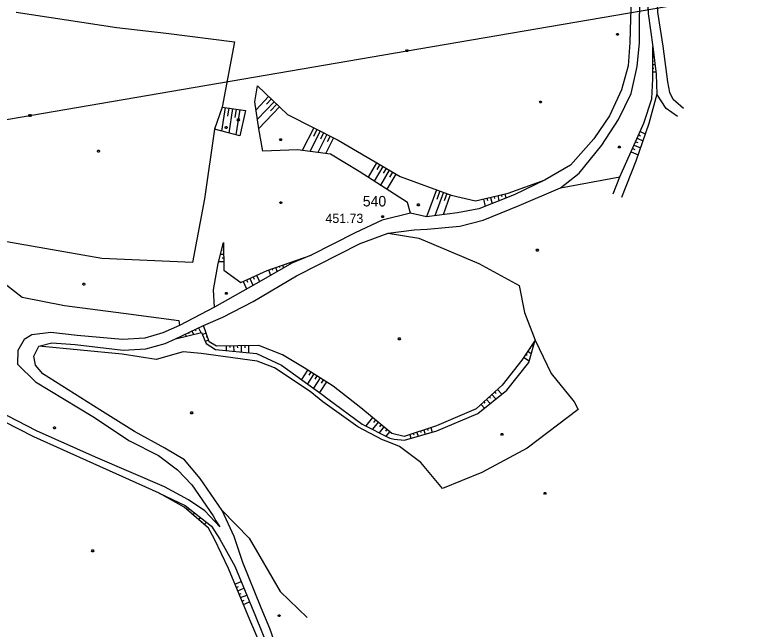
# Model space of a CAD drawing. Extents: x -664960 to -662754, y -993849 to -991145.
# Drawn here: x -662991.3 to -662754.2, y -992772.1 to -992572.6 of the extents above; entities that cross this region are included whole.
import ezdxf

# ---------------------------------------------------------------- set-up
doc = ezdxf.new("R2010")
doc.units = 0
for name, color, linetype in [('Vrstva 1', 7, 'Continuous'), ('Vrstva 13', 7, 'Continuous'), ('Vrstva 27', 7, 'Continuous'), ('Vrstva 37', 7, 'Continuous'), ('Vrstva 57', 7, 'Continuous'), ('Vrstva 63', 7, 'Continuous'), ('Vrstva 8', 7, 'Continuous')]:
    doc.layers.add(name, color=color, linetype=linetype)

msp = doc.modelspace()

# ---------------------------------------------------------------- linework, layer by layer
at = {"layer": 'Vrstva 13'}
for points in [[(-662820.269, -992600.671), (-662820.089, -992600.971), (-662820.269, -992601.271), (-662820.629, -992601.271), (-662820.809, -992600.971), (-662820.629, -992600.671), (-662820.269, -992600.671)], [(-662904.678, -992612.889), (-662904.498, -992613.189), (-662904.678, -992613.489), (-662905.038, -992613.489), (-662905.218, -992613.189), (-662905.038, -992612.889), (-662904.678, -992612.889)], [(-662794.695, -992615.239), (-662794.515, -992615.539), (-662794.695, -992615.839), (-662795.055, -992615.839), (-662795.235, -992615.539), (-662795.055, -992615.239), (-662794.695, -992615.239)], [(-662963.83, -992616.631), (-662963.65, -992616.931), (-662963.83, -992617.231), (-662964.19, -992617.231), (-662964.37, -992616.931), (-662964.19, -992616.631), (-662963.83, -992616.631)], [(-662904.616, -992633.337), (-662904.436, -992633.637), (-662904.616, -992633.937), (-662904.976, -992633.937), (-662905.156, -992633.637), (-662904.976, -992633.337), (-662904.616, -992633.337)], [(-662859.938, -992634.055), (-662859.758, -992634.355), (-662859.938, -992634.655), (-662860.298, -992634.655), (-662860.478, -992634.355), (-662860.298, -992634.055), (-662859.938, -992634.055)], [(-662821.298, -992648.724), (-662821.118, -992649.024), (-662821.298, -992649.324), (-662821.658, -992649.324), (-662821.838, -992649.024), (-662821.658, -992648.724), (-662821.298, -992648.724)], [(-662968.594, -992659.789), (-662968.414, -992660.089), (-662968.594, -992660.389), (-662968.954, -992660.389), (-662969.134, -992660.089), (-662968.954, -992659.789), (-662968.594, -992659.789)], [(-662922.343, -992662.749), (-662922.163, -992663.049), (-662922.343, -992663.349), (-662922.703, -992663.349), (-662922.883, -992663.049), (-662922.703, -992662.749), (-662922.343, -992662.749)], [(-662866.16, -992677.539), (-662865.98, -992677.839), (-662866.16, -992678.139), (-662866.52, -992678.139), (-662866.7, -992677.839), (-662866.52, -992677.539), (-662866.16, -992677.539)], [(-662933.542, -992701.554), (-662933.362, -992701.854), (-662933.542, -992702.154), (-662933.902, -992702.154), (-662934.082, -992701.854), (-662933.902, -992701.554), (-662933.542, -992701.554)], [(-662978.123, -992706.427), (-662977.943, -992706.727), (-662978.123, -992707.027), (-662978.483, -992707.027), (-662978.663, -992706.727), (-662978.483, -992706.427), (-662978.123, -992706.427)], [(-662832.81, -992708.515), (-662832.63, -992708.815), (-662832.81, -992709.115), (-662833.17, -992709.115), (-662833.35, -992708.815), (-662833.17, -992708.515), (-662832.81, -992708.515)], [(-662818.857, -992727.658), (-662818.677, -992727.958), (-662818.857, -992728.258), (-662819.217, -992728.258), (-662819.397, -992727.958), (-662819.217, -992727.658), (-662818.857, -992727.658)], [(-662965.695, -992746.303), (-662965.515, -992746.603), (-662965.695, -992746.903), (-662966.055, -992746.903), (-662966.235, -992746.603), (-662966.055, -992746.303), (-662965.695, -992746.303)], [(-662905.166, -992767.399), (-662904.986, -992767.699), (-662905.166, -992767.999), (-662905.526, -992767.999), (-662905.706, -992767.699), (-662905.526, -992767.399), (-662905.166, -992767.399)]]:
    msp.add_lwpolyline(points, dxfattribs=at)
at = {"layer": 'Vrstva 27'}
for points in [[(-662783.31, -992523.58), (-662785.46, -992536.18), (-662786.51, -992550.42), (-662785.54, -992572.27), (-662783.94, -992583.1)], [(-662814.02, -992628.77), (-662807.9, -992624.04), (-662800.53, -992615), (-662795.19, -992606.64), (-662791.07, -992598.2), (-662789.03, -992589.4), (-662788.34, -992581.72), (-662788.3, -992573.38), (-662787.39, -992550.45), (-662786.57, -992536.01), (-662787.99, -992526.89)], [(-662773.98, -992603.1), (-662777.38, -992600.19), (-662778.5, -992597.92), (-662779.16, -992594.44), (-662780.59, -992582.88), (-662782.36, -992571.76), (-662783.36, -992550.29), (-662782.46, -992536.59), (-662780.37, -992526.63)], [(-662790.37, -992550.8), (-662791.29, -992573.99), (-662791.42, -992581.67), (-662792.03, -992589.2), (-662794.12, -992596.99), (-662798.03, -992605.48), (-662803.2, -992612.92), (-662810.72, -992621.51), (-662818.96, -992626.26)], [(-662775.95, -992605.62), (-662779.61, -992603.11), (-662782.69, -992598.42)], [(-662839.12, -992639.35), (-662827.35, -992634.53), (-662814.02, -992628.77)], [(-662862.68, -992637.01), (-662871.9, -992639.26), (-662880.6, -992643.45), (-662894.95, -992650.64)], [(-662920, -992741.98), (-662923.87, -992733.57), (-662931.03, -992723.19), (-662936.1, -992717.15), (-662942.41, -992713.3), (-662952.34, -992707.86), (-662963.59, -992700.84), (-662982.13, -992689.15), (-662984.42, -992686.38), (-662985.05, -992683.42), (-662983.4, -992680.23), (-662979.18, -992679.11), (-662971.61, -992679.66), (-662956.04, -992681.53), (-662948.6, -992681.11), (-662942.34, -992679.34), (-662939.04, -992677.84), (-662929.94, -992673.49), (-662923.58, -992670.74), (-662913.79, -992665.67), (-662899.69, -992657.43), (-662879.01, -992646.88), (-662869.94, -992643.5), (-662861.52, -992642.43), (-662857.22, -992642.21), (-662846.7, -992641.27), (-662839.12, -992639.35)], [(-662926.37, -992667.52), (-662937.65, -992673.51), (-662943.13, -992675.85), (-662949, -992677.64), (-662956.17, -992678.08), (-662970.95, -992676.78), (-662979.5, -992675.73), (-662985.63, -992676.49), (-662988.09, -992678.08), (-662990.2, -992681.58), (-662990.26, -992686.06), (-662984.45, -992691.79), (-662965.81, -992703.08), (-662953.95, -992710.94), (-662944.54, -992715.73), (-662938.37, -992720.36), (-662933.71, -992725.23), (-662926.81, -992735.29), (-662925.91, -992736.91), (-662924.58, -992738.79)], [(-662899.77, -992799.69), (-662904.47, -992782.92), (-662908.32, -992771.87), (-662911.16, -992765.16), (-662917.17, -992750.4), (-662920, -992741.98)]]:
    msp.add_lwpolyline(points, dxfattribs=at)
at = {"layer": 'Vrstva 37'}
for points in [[(-662863.64, -992584.02), (-662863.46, -992584.32), (-662863.64, -992584.62), (-662864, -992584.62), (-662864.18, -992584.32), (-662864, -992584.02), (-662863.64, -992584.02)], [(-662986.1, -992605.06), (-662985.92, -992605.36), (-662986.1, -992605.66), (-662986.46, -992605.66), (-662986.64, -992605.36), (-662986.46, -992605.06), (-662986.1, -992605.06)]]:
    msp.add_lwpolyline(points, dxfattribs=at)
at = {"layer": 'Vrstva 57'}
msp.add_lwpolyline([(-663665.051, -992722.016), (-663550.65, -992702.35), (-663440.01, -992683.39), (-663326.32, -992663.75), (-663217.09, -992644.97), (-663109.78, -992626.53), (-662986.28, -992605.36), (-662863.82, -992584.32), (-662754.25, -992565.49)], dxfattribs=at)
at = {"layer": 'Vrstva 63'}
for p, q in [((-662783.958, -992585.146), (-662783.871, -992585.147)), ((-662783.947, -992583.946), (-662783.84, -992583.947)), ((-662783.979, -992587.546), (-662783.79, -992587.547)), ((-662783.968, -992586.346), (-662783.555, -992586.349)), ((-662783.999, -992589.946), (-662783.709, -992589.948)), ((-662783.989, -992588.746), (-662783.27, -992588.752)), ((-662784.01, -992591.146), (-662782.985, -992591.155)), ((-662908.75, -992599.197), (-662912.826, -992603.488)), ((-662907.01, -992600.85), (-662912.374, -992606.497)), ((-662907.88, -992600.024), (-662909.452, -992601.678)), ((-662906.14, -992601.677), (-662908.141, -992603.783)), ((-662922.877, -992602.728), (-662924.023, -992610.412)), ((-662921.69, -992602.904), (-662922.078, -992605.506)), ((-662920.503, -992603.081), (-662921.687, -992611.022)), ((-662919.317, -992603.258), (-662919.717, -992605.945)), ((-662918.13, -992603.435), (-662919.352, -992611.633)), ((-662905.27, -992602.503), (-662911.923, -992609.507)), ((-662894.121, -992609.308), (-662897.856, -992616.719)), ((-662891.978, -992610.388), (-662895.338, -992617.055)), ((-662893.05, -992609.848), (-662894.231, -992612.192)), ((-662889.835, -992611.468), (-662892.82, -992617.391)), ((-662890.906, -992610.928), (-662891.963, -992613.024)), ((-662788.076, -992610.558), (-662786.46, -992611.281)), ((-662887.692, -992612.548), (-662890.302, -992617.728)), ((-662888.763, -992612.008), (-662889.695, -992613.857)), ((-662789.545, -992613.845), (-662788.908, -992614.13)), ((-662789.055, -992612.749), (-662787.241, -992613.561)), ((-662788.565, -992611.654), (-662787.994, -992611.909)), ((-662790.525, -992616.036), (-662789.821, -992616.35)), ((-662790.035, -992614.94), (-662788.021, -992615.841)), ((-662791.015, -992617.131), (-662788.802, -992618.121)), ((-662873.698, -992620.671), (-662876.471, -992625.374)), ((-662871.63, -992621.89), (-662874.45, -992626.67)), ((-662872.664, -992621.281), (-662873.595, -992622.859)), ((-662869.563, -992623.11), (-662872.428, -992627.967)), ((-662870.597, -992622.5), (-662871.543, -992624.104)), ((-662867.496, -992624.329), (-662870.406, -992629.263)), ((-662868.53, -992623.719), (-662869.491, -992625.349)), ((-662814.02, -992628.77), (-662794.65, -992625.26)), ((-662854.27, -992629.426), (-662857.46, -992638.27)), ((-662852.013, -992630.24), (-662854.777, -992637.906)), ((-662853.141, -992629.833), (-662854.133, -992632.582)), ((-662849.755, -992631.054), (-662852.095, -992637.543)), ((-662850.884, -992630.647), (-662851.734, -992633.004)), ((-662839.031, -992632.459), (-662838.463, -992634.861)), ((-662837.863, -992632.183), (-662837.687, -992632.927)), ((-662836.695, -992631.907), (-662836.206, -992633.974)), ((-662835.528, -992631.63), (-662835.378, -992632.263)), ((-662834.36, -992631.354), (-662833.95, -992633.087)), ((-662833.192, -992631.078), (-662833.069, -992631.599)), ((-662832.024, -992630.802), (-662831.694, -992632.2)), ((-662923.394, -992648.007), (-662923.783, -992648.011)), ((-662923.381, -992649.207), (-662923.619, -992649.209)), ((-662923.367, -992650.407), (-662924.409, -992650.418)), ((-662923.354, -992651.607), (-662923.81, -992651.612)), ((-662923.341, -992652.807), (-662925.036, -992652.825)), ((-662904.228, -992653.869), (-662903.909, -992654.785)), ((-662903.095, -992653.474), (-662903.013, -992653.71)), ((-662901.961, -992653.08), (-662901.788, -992653.578)), ((-662908.761, -992655.446), (-662908.151, -992657.2)), ((-662907.628, -992655.052), (-662907.449, -992655.566)), ((-662906.495, -992654.658), (-662906.03, -992655.992)), ((-662905.361, -992654.263), (-662905.231, -992654.638)), ((-662915.946, -992658.704), (-662915.591, -992659.474)), ((-662914.857, -992658.202), (-662913.832, -992660.423)), ((-662913.767, -992657.699), (-662913.44, -992658.409)), ((-662912.677, -992657.196), (-662911.736, -992659.237)), ((-662917.036, -992659.207), (-662915.928, -992661.609)), ((-662933.677, -992675.276), (-662933.14, -992676.4)), ((-662932.595, -992674.759), (-662932.38, -992675.209)), ((-662931.512, -992674.241), (-662930.758, -992675.818)), ((-662938.008, -992677.347), (-662937.905, -992677.563)), ((-662936.925, -992676.829), (-662936.855, -992676.977)), ((-662935.843, -992676.312), (-662935.522, -992676.981)), ((-662934.76, -992675.794), (-662934.617, -992676.093)), ((-662929.05, -992676.014), (-662930.275, -992676.446)), ((-662928.651, -992677.146), (-662929.036, -992677.282)), ((-662928.251, -992678.277), (-662929.342, -992678.662)), ((-662922.525, -992680.147), (-662922.505, -992681.644)), ((-662921.325, -992680.13), (-662921.318, -992680.673)), ((-662920.126, -992680.113), (-662920.101, -992681.876)), ((-662918.926, -992680.097), (-662918.917, -992680.728)), ((-662917.726, -992680.08), (-662917.698, -992682.109)), ((-662916.526, -992680.064), (-662916.516, -992680.783)), ((-662915.326, -992680.047), (-662915.294, -992682.341)), ((-662823.261, -992679.841), (-662822.765, -992680.176)), ((-662824.604, -992681.83), (-662823.468, -992682.598)), ((-662823.933, -992680.836), (-662823.661, -992681.019)), ((-662825.948, -992683.819), (-662824.172, -992685.019)), ((-662825.276, -992682.825), (-662824.791, -992683.152)), ((-662896.102, -992687.942), (-662898.04, -992691.047)), ((-662894.066, -992689.213), (-662896.09, -992692.456)), ((-662895.084, -992688.577), (-662895.744, -992689.634)), ((-662892.03, -992690.484), (-662894.14, -992693.864)), ((-662893.048, -992689.848), (-662893.736, -992690.951)), ((-662889.994, -992691.755), (-662892.191, -992695.273)), ((-662891.012, -992691.12), (-662891.729, -992692.268)), ((-662834.475, -992694.241), (-662833.056, -992695.784)), ((-662837.125, -992696.677), (-662836.708, -992697.131)), ((-662836.242, -992695.865), (-662834.934, -992697.288)), ((-662835.358, -992695.053), (-662834.904, -992695.547)), ((-662839.776, -992699.114), (-662838.689, -992700.295)), ((-662838.892, -992698.301), (-662838.512, -992698.715)), ((-662838.009, -992697.489), (-662836.811, -992698.792)), ((-662874.98, -992703.345), (-662877.227, -992706.044)), ((-662873.136, -992704.881), (-662875.043, -992707.171)), ((-662874.058, -992704.113), (-662874.75, -992704.944)), ((-662872.214, -992705.649), (-662872.792, -992706.343)), ((-662871.292, -992706.417), (-662872.858, -992708.297)), ((-662870.37, -992707.185), (-662870.834, -992707.743)), ((-662869.447, -992707.953), (-662870.673, -992709.424)), ((-662861.768, -992708.546), (-662861.636, -992708.954)), ((-662860.627, -992708.175), (-662860.215, -992709.444)), ((-662859.485, -992707.805), (-662859.344, -992708.242)), ((-662858.344, -992707.435), (-662857.904, -992708.789)), ((-662857.202, -992707.064), (-662857.051, -992707.529)), ((-662856.061, -992706.694), (-662855.594, -992708.134)), ((-662862.91, -992708.916), (-662862.526, -992710.099)), ((-662935.109, -992733.418), (-662934.62, -992732.847)), ((-662934.198, -992734.199), (-662934.025, -992733.997)), ((-662933.286, -992734.979), (-662932.738, -992734.339)), ((-662932.375, -992735.76), (-662932.182, -992735.535)), ((-662931.463, -992736.54), (-662930.855, -992735.83)), ((-662930.552, -992737.321), (-662930.339, -992737.073)), ((-662929.64, -992738.101), (-662928.973, -992737.322)), ((-662919.712, -992757.398), (-662917.719, -992756.567)), ((-662919.249, -992758.506), (-662918.587, -992758.229)), ((-662918.787, -992759.613), (-662916.8, -992758.784)), ((-662918.325, -992760.721), (-662917.664, -992760.445)), ((-662917.863, -992761.828), (-662915.882, -992761.001)), ((-662917.401, -992762.936), (-662916.742, -992762.661)), ((-662916.939, -992764.043), (-662914.963, -992763.219))]:
    msp.add_line(p, q, dxfattribs=at)
for points in [[(-662990.76, -992571.78), (-662958.07, -992576.73), (-662942, -992578.62), (-662919.89, -992581.4)], [(-662795.28, -992578.68), (-662795.1, -992578.98), (-662795.28, -992579.28), (-662795.64, -992579.28), (-662795.82, -992578.98), (-662795.64, -992578.68), (-662795.28, -992578.68)], [(-662919.89, -992581.4), (-662923.8, -992602.59), (-662926.29, -992609.82), (-662929.54, -992632.43), (-662933.44, -992653.09), (-662962.95, -992651.77), (-663008.75, -992643.79), (-663010.79, -992650.95), (-662996.35, -992658.42), (-662988.75, -992664.27), (-662975.04, -992667.06), (-662955.87, -992669.48), (-662937.89, -992671.86), (-662937.65, -992673.51)], [(-662796.86, -992630.73), (-662794.65, -992625.26), (-662786.86, -992607.84), (-662784.28, -992599.95), (-662784.03, -992593.49), (-662783.94, -992583.1)], [(-662783.94, -992583.1), (-662782.9, -992591.87), (-662782.69, -992598.42), (-662785.32, -992607.95), (-662789.5, -992620.16), (-662794.16, -992631.95)], [(-662912.39, -992595.74), (-662902.61, -992605.03), (-662886.16, -992613.32), (-662866.07, -992625.17), (-662849.49, -992631.15), (-662841.53, -992633.05), (-662830.96, -992630.55), (-662818.96, -992626.26), (-662828.97, -992631.13), (-662840.47, -992635.65), (-662847.43, -992636.91), (-662857.46, -992638.27), (-662862.68, -992637.01), (-662863.69, -992633.57), (-662879.3, -992623.56), (-662888.71, -992617.94), (-662899.35, -992616.52), (-662910.6, -992616.94), (-662911.9, -992609.66), (-662913.22, -992600.86), (-662912.39, -992595.74)], [(-662923.8, -992602.59), (-662916.22, -992603.72), (-662918.06, -992611.97), (-662926.29, -992609.82)], [(-662918.44, -992606.46), (-662918.26, -992606.76), (-662918.44, -992607.06), (-662918.8, -992607.06), (-662918.98, -992606.76), (-662918.8, -992606.46), (-662918.44, -992606.46)], [(-662922.38, -992608.93), (-662922.2, -992609.23), (-662922.38, -992609.53), (-662922.74, -992609.53), (-662922.92, -992609.23), (-662922.74, -992608.93), (-662922.38, -992608.93)], [(-662869.94, -992643.5), (-662859.93, -992645.19), (-662840.5, -992653.4), (-662827.38, -992660.51), (-662825.65, -992669.23), (-662822.22, -992678.3), (-662826.57, -992684.74), (-662832.94, -992692.83), (-662841.36, -992700.57), (-662854.2, -992706.09), (-662864.74, -992709.51), (-662868.79, -992708.5), (-662878.77, -992700.19), (-662887.76, -992693.15), (-662897.21, -992687.25), (-662904.27, -992683.06), (-662911.9, -992680), (-662925.68, -992680.19), (-662928.06, -992678.82), (-662929.94, -992673.49)], [(-662894.95, -992650.64), (-662901.23, -992653.26), (-662910.47, -992658.52), (-662926.37, -992667.52), (-662926.61, -992661.92), (-662925.17, -992653.34), (-662923.41, -992646.58), (-662923.31, -992655.55), (-662917.78, -992659.55), (-662909.26, -992655.62), (-662894.95, -992650.64)], [(-662939.04, -992677.84), (-662930.56, -992675.77), (-662929.04, -992679.38), (-662925.96, -992681.31), (-662912.72, -992682.59), (-662904.57, -992686.33), (-662891.35, -992695.88), (-662889.49, -992697.35), (-662878.34, -992705.47), (-662869.44, -992710.06), (-662867.96, -992710.36), (-662864.68, -992710.71), (-662854.17, -992707.73), (-662840.83, -992702.01), (-662831.44, -992694.49), (-662824.3, -992685.46), (-662822.22, -992678.3)], [(-662822.22, -992678.3), (-662817, -992689.08), (-662809.5, -992698.27), (-662808.28, -992700.79), (-662824.82, -992713.31), (-662839.57, -992721.25), (-662852.25, -992726.37), (-662859.36, -992718.01), (-662866.21, -992712.78), (-662870.31, -992711.2), (-662871.81, -992710.66), (-662879.76, -992706.39), (-662891.13, -992698.27), (-662895.31, -992694.9), (-662906.87, -992687.29), (-662912.49, -992685.05), (-662930.62, -992682.62), (-662936.48, -992682.03), (-662945.3, -992684.52), (-662956.32, -992682.79), (-662983.4, -992680.23)], [(-662924.58, -992738.79), (-662929.43, -992733.69), (-662934.74, -992730.07), (-662942.55, -992725.85), (-662964.98, -992716.24), (-662984.1, -992707.69), (-663003.04, -992697.94), (-663011.58, -992691.58), (-663018.16, -992685.44)], [(-662944.35, -992727.89), (-662965.7, -992718.3), (-662984.99, -992709.67), (-663004.41, -992699.77), (-663010.91, -992696.38)], [(-662944.35, -992727.89), (-662935.84, -992731.88), (-662927.36, -992738.6), (-662924.55, -992742.87), (-662919.76, -992751.64), (-662913.04, -992767.86), (-662907.28, -992782.02), (-662903.51, -992795.55), (-662906.41, -992791.88), (-662909.11, -992782.39), (-662914.87, -992769), (-662921.81, -992752.37), (-662926.29, -992742.83), (-662928.31, -992739.24), (-662936.17, -992732.51), (-662944.35, -992727.89)], [(-662923.87, -992733.57), (-662915.05, -992742.54), (-662904.96, -992759.8), (-662896.21, -992768.32)]]:
    msp.add_lwpolyline(points, dxfattribs=at)
at = {"layer": 'Vrstva 8'}
msp.add_lwpolyline([(-662871.51, -992637.89), (-662871.33, -992638.19), (-662871.51, -992638.49), (-662871.87, -992638.49), (-662872.05, -992638.19), (-662871.87, -992637.89), (-662871.51, -992637.89)], dxfattribs=at)

# ---------------------------------------------------------------- texts
at = {"layer": 'Vrstva 1'}
msp.add_text('540', height=3.4, dxfattribs=at).set_placement((-662878.169, -992634.858))
at = {"layer": 'Vrstva 63'}
msp.add_text('451.73', height=3, dxfattribs=at).set_placement((-662890.29, -992640.232))

doc.saveas('drawing.dxf')
